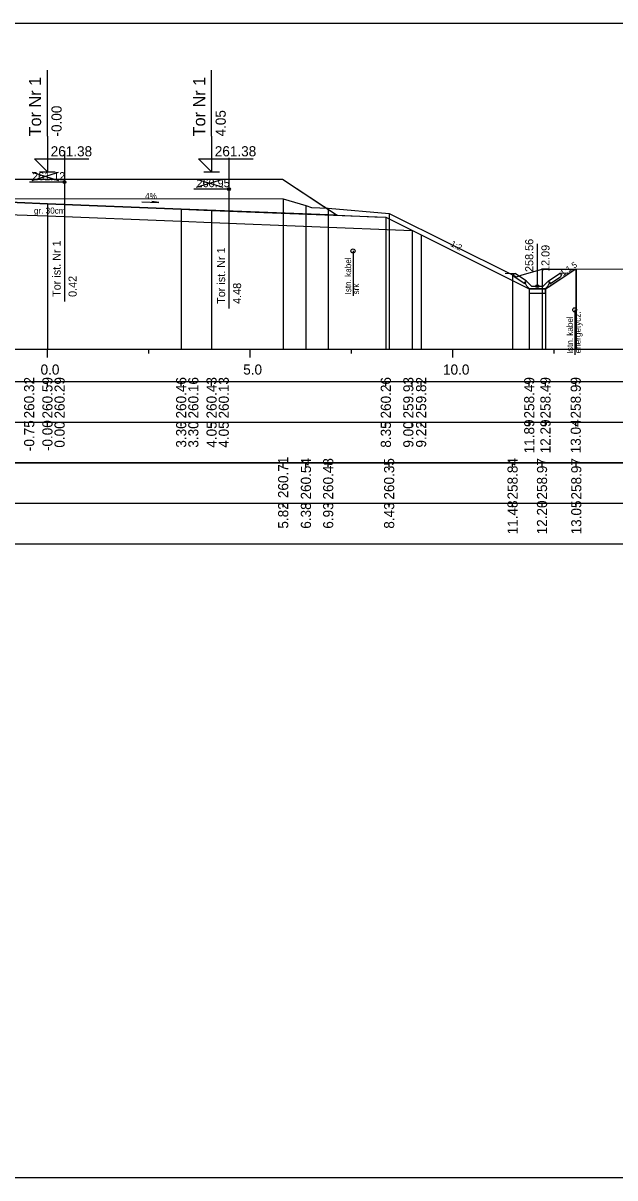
# Model space of a CAD drawing. Extents: x 6516023 to 6560129, y 5513077 to 5529206.
# Drawn here: x 6517492.86 to 6517507.46, y 5514484.66 to 5514513.16 of the extents above; entities that cross this region are included whole.
import ezdxf

# ---------------------------------------------------------------- set-up
doc = ezdxf.new("R2010")
doc.units = 0
for name, color, linetype in [('IR_default', 7, 'Continuous'), ('TOR_PRZEK_P-kable', 7, 'Continuous'), ('TOR_PRZEK_P-komponent', 7, 'Continuous'), ('TOR_PRZEK_P-odwodnienie', 7, 'Continuous'), ('TOR_PRZEK_P-opisy', 7, 'Continuous'), ('TOR_PRZEK_P-tabelka istniejace', 7, 'Continuous'), ('TOR_PRZEK_P-tabelka projektowane', 7, 'Continuous'), ('TOR_PRZEK_P-teren istniejacy', 7, 'Continuous'), ('TOR_PRZEK_P-tory istniejace', 7, 'Continuous'), ('TOR_PRZEK_P-tory projektowane', 7, 'Continuous'), ('TOR_PRZEK_P-uklad odniesienia', 7, 'Continuous'), ('TOR_PRZEK_P-warstwa ochronna I', 7, 'Continuous'), ('TOR_PRZEK_P-warstwa ochronna II', 7, 'Continuous'), ('TOR_RAMKI-ramka+tabelka 1', 7, 'Continuous')]:
    doc.layers.add(name, color=color, linetype=linetype)

msp = doc.modelspace()

# ---------------------------------------------------------------- linework, layer by layer
at = {"layer": 'IR_default'}
msp.add_lwpolyline([(6517491.713, 5514509.307), (6517494.429, 5514509.307), (6517495.213, 5514509.307), (6517495.336, 5514509.308), (6517495.763, 5514509.308), (6517498.479, 5514509.308), (6517499.263, 5514509.308), (6517500.307, 5514508.613), (6517500.608, 5514508.412), (6517501.543, 5514508.374), (6517501.813, 5514508.363), (6517502.488, 5514508.026), (6517502.683, 5514507.929), (6517503.278, 5514507.631), (6517505.352, 5514506.594), (6517505.441, 5514506.594), (6517505.752, 5514506.594), (6517505.883, 5514506.681), (6517506.337, 5514506.984), (6517506.373, 5514507.008), (6517506.499, 5514507.092)], dxfattribs=at)
at = {"layer": 'TOR_PRZEK_P-kable'}
for p, q in [((6517501.003, 5514507.533), (6517501.003, 5514506.423)), ((6517506.474, 5514506.08), (6517506.474, 5514504.97))]:
    msp.add_line(p, q, dxfattribs=at)
for centre in [(6517501.003, 5514507.533), (6517506.474, 5514506.08)]:
    msp.add_circle(centre, 0.05, dxfattribs=at)
at = {"layer": 'TOR_PRZEK_P-komponent'}
msp.add_lwpolyline([(6517487.213, 5514509.307), (6517490.713, 5514509.307), (6517491.713, 5514509.307), (6517495.213, 5514509.307), (6517495.763, 5514509.308), (6517499.263, 5514509.308), (6517500.608, 5514508.412), (6517496.763, 5514508.565), (6517493.463, 5514508.697), (6517492.713, 5514508.727), (6517491.513, 5514508.775), (6517490.913, 5514508.775), (6517489.713, 5514508.727), (6517488.963, 5514508.697), (6517486.128, 5514508.584)], close=True, dxfattribs=at)
at = {"layer": 'TOR_PRZEK_P-odwodnienie'}
for p, q in [((6517505.551, 5514506.664), (6517505.551, 5514507.708)), ((6517505.242, 5514506.723), (6517504.981, 5514506.897)), ((6517505.287, 5514506.79), (6517505.006, 5514506.977)), ((6517505.816, 5514506.79), (6517506.096, 5514506.977)), ((6517505.86, 5514506.723), (6517506.122, 5514506.897)), ((6517505.253, 5514506.74), (6517505.242, 5514506.723)), ((6517505.244, 5514506.759), (6517505.291, 5514506.783)), ((6517505.287, 5514506.79), (6517505.278, 5514506.777)), ((6517505.411, 5514506.664), (6517505.291, 5514506.783)), ((6517505.411, 5514506.664), (6517505.691, 5514506.664)), ((6517505.691, 5514506.664), (6517505.811, 5514506.783)), ((6517505.811, 5514506.783), (6517505.859, 5514506.759)), ((6517505.816, 5514506.79), (6517505.824, 5514506.777)), ((6517505.849, 5514506.74), (6517505.86, 5514506.723)), ((6517505.361, 5514506.594), (6517505.741, 5514506.594))]:
    msp.add_line(p, q, dxfattribs=at)
for points in [[(6517504.76, 5514506.988), (6517505.006, 5514506.977)], [(6517504.956, 5514506.95), (6517505.006, 5514506.977)], [(6517504.956, 5514506.95), (6517504.981, 5514506.897)], [(6517506.343, 5514506.988), (6517506.096, 5514506.977)], [(6517506.147, 5514506.95), (6517506.096, 5514506.977)], [(6517506.147, 5514506.95), (6517506.122, 5514506.897)], [(6517505.278, 5514506.777), (6517505.243, 5514506.759)], [(6517505.243, 5514506.759), (6517505.253, 5514506.74)], [(6517505.291, 5514506.664), (6517505.244, 5514506.759)], [(6517505.361, 5514506.594), (6517505.291, 5514506.664)], [(6517505.741, 5514506.594), (6517505.811, 5514506.664)], [(6517505.811, 5514506.664), (6517505.859, 5514506.759)], [(6517505.824, 5514506.777), (6517505.859, 5514506.759)], [(6517505.859, 5514506.759), (6517505.849, 5514506.74)], [(6517505.352, 5514506.594), (6517505.351, 5514506.595), (6517505.352, 5514506.594), (6517505.351, 5514506.594), (6517505.352, 5514506.594), (6517505.352, 5514506.594), (6517505.352, 5514506.594), (6517505.352, 5514506.595)], [(6517505.351, 5514506.594), (6517505.351, 5514506.594), (6517505.351, 5514506.594), (6517505.351, 5514506.593), (6517505.351, 5514506.594), (6517505.352, 5514506.593), (6517505.351, 5514506.594), (6517505.352, 5514506.594)], [(6517505.751, 5514506.594), (6517505.351, 5514506.594), (6517505.351, 5514506.494), (6517505.751, 5514506.494), (6517505.751, 5514506.594)], [(6517505.752, 5514506.594), (6517505.751, 5514506.595), (6517505.752, 5514506.594), (6517505.751, 5514506.594), (6517505.752, 5514506.594), (6517505.752, 5514506.594), (6517505.752, 5514506.594), (6517505.752, 5514506.595)], [(6517505.751, 5514506.594), (6517505.751, 5514506.594), (6517505.751, 5514506.594), (6517505.751, 5514506.593), (6517505.751, 5514506.594), (6517505.752, 5514506.593), (6517505.751, 5514506.594), (6517505.752, 5514506.594)]]:
    msp.add_lwpolyline(points, dxfattribs=at)
msp.add_circle((6517505.551, 5514506.664), 0.035, dxfattribs=at)
at = {"layer": 'TOR_PRZEK_P-opisy'}
msp.add_lwpolyline([(6517495.793, 5514508.745), (6517496.211, 5514508.726), (6517496.043, 5514508.754)], dxfattribs=at)
at = {"layer": 'TOR_PRZEK_P-tabelka istniejace'}
for p, q in [((6517499.28, 5514502.206), (6517499.28, 5514502.306)), ((6517499.841, 5514502.206), (6517499.841, 5514502.306)), ((6517500.39, 5514502.206), (6517500.39, 5514502.306)), ((6517501.894, 5514502.206), (6517501.894, 5514502.306)), ((6517504.94, 5514502.206), (6517504.94, 5514502.306)), ((6517505.666, 5514502.206), (6517505.666, 5514502.306)), ((6517506.512, 5514502.206), (6517506.512, 5514502.306)), ((6517454.663, 5514501.306), (6517538.463, 5514501.306)), ((6517499.28, 5514501.206), (6517499.28, 5514501.306)), ((6517499.841, 5514501.206), (6517499.841, 5514501.306)), ((6517500.39, 5514501.206), (6517500.39, 5514501.306)), ((6517501.894, 5514501.206), (6517501.894, 5514501.306)), ((6517504.94, 5514501.206), (6517504.94, 5514501.306)), ((6517505.666, 5514501.206), (6517505.666, 5514501.306)), ((6517506.512, 5514501.206), (6517506.512, 5514501.306))]:
    msp.add_line(p, q, dxfattribs=at)
for points in [[(6517499.28, 5514508.82), (6517499.28, 5514505.306), (6517499.28, 5514505.176), (6517499.28, 5514505.106)], [(6517499.841, 5514508.651), (6517499.841, 5514505.306), (6517499.841, 5514505.176), (6517499.841, 5514505.106)], [(6517500.39, 5514508.585), (6517500.39, 5514505.306), (6517500.39, 5514505.176), (6517500.39, 5514505.106)], [(6517501.894, 5514508.456), (6517501.894, 5514505.306), (6517501.894, 5514505.176), (6517501.894, 5514505.106)], [(6517504.94, 5514506.944), (6517504.94, 5514505.306), (6517504.94, 5514505.176), (6517504.94, 5514505.106)], [(6517505.666, 5514507.08), (6517505.666, 5514505.306), (6517505.666, 5514505.176), (6517505.666, 5514505.106)], [(6517506.512, 5514507.08), (6517506.512, 5514505.306), (6517506.512, 5514505.176), (6517506.512, 5514505.106)]]:
    msp.add_lwpolyline(points, dxfattribs=at)
msp.add_lwpolyline([(6517454.663, 5514502.306), (6517454.663, 5514500.306), (6517538.463, 5514500.306), (6517538.463, 5514502.306)], close=True, dxfattribs=at)
at = {"layer": 'TOR_PRZEK_P-tabelka projektowane'}
for p, q in [((6517493.463, 5514504.206), (6517493.463, 5514504.306)), ((6517493.463, 5514504.206), (6517493.463, 5514504.306)), ((6517496.763, 5514504.206), (6517496.763, 5514504.306)), ((6517496.763, 5514504.206), (6517496.763, 5514504.306)), ((6517497.513, 5514504.206), (6517497.513, 5514504.306)), ((6517497.513, 5514504.206), (6517497.513, 5514504.306)), ((6517501.813, 5514504.206), (6517501.813, 5514504.306)), ((6517502.465, 5514504.206), (6517502.465, 5514504.306)), ((6517502.683, 5514504.206), (6517502.683, 5514504.306)), ((6517505.351, 5514504.206), (6517505.351, 5514504.306)), ((6517505.751, 5514504.206), (6517505.751, 5514504.306)), ((6517506.498, 5514504.206), (6517506.498, 5514504.306)), ((6517454.663, 5514503.306), (6517538.463, 5514503.306)), ((6517493.463, 5514503.206), (6517493.463, 5514503.306)), ((6517493.463, 5514503.206), (6517493.463, 5514503.306)), ((6517496.763, 5514503.206), (6517496.763, 5514503.306)), ((6517496.763, 5514503.206), (6517496.763, 5514503.306)), ((6517497.513, 5514503.206), (6517497.513, 5514503.306)), ((6517497.513, 5514503.206), (6517497.513, 5514503.306)), ((6517501.813, 5514503.206), (6517501.813, 5514503.306)), ((6517502.465, 5514503.206), (6517502.465, 5514503.306)), ((6517502.683, 5514503.206), (6517502.683, 5514503.306)), ((6517505.351, 5514503.206), (6517505.351, 5514503.306)), ((6517505.751, 5514503.206), (6517505.751, 5514503.306)), ((6517506.498, 5514503.206), (6517506.498, 5514503.306))]:
    msp.add_line(p, q, dxfattribs=at)
for points in [[(6517493.463, 5514508.697), (6517493.463, 5514505.306), (6517493.463, 5514505.176), (6517493.463, 5514505.106)], [(6517493.463, 5514508.397), (6517493.463, 5514505.306), (6517493.463, 5514505.176), (6517493.463, 5514505.106)], [(6517496.763, 5514508.565), (6517496.763, 5514505.306), (6517496.763, 5514505.176), (6517496.763, 5514505.106)], [(6517497.513, 5514508.535), (6517497.513, 5514505.306), (6517497.513, 5514505.176), (6517497.513, 5514505.106)], [(6517501.813, 5514508.363), (6517501.813, 5514505.306), (6517501.813, 5514505.176), (6517501.813, 5514505.106)], [(6517496.763, 5514508.265), (6517496.763, 5514505.306), (6517496.763, 5514505.176), (6517496.763, 5514505.106)], [(6517497.513, 5514508.235), (6517497.513, 5514505.306), (6517497.513, 5514505.176), (6517497.513, 5514505.106)], [(6517502.465, 5514508.037), (6517502.465, 5514505.306), (6517502.465, 5514505.176), (6517502.465, 5514505.106)], [(6517502.683, 5514507.928), (6517502.683, 5514505.306), (6517502.683, 5514505.176), (6517502.683, 5514505.106)], [(6517506.498, 5514507.092), (6517506.498, 5514505.306), (6517506.498, 5514505.176), (6517506.498, 5514505.106)], [(6517505.351, 5514506.594), (6517505.351, 5514505.306), (6517505.351, 5514505.176), (6517505.351, 5514505.106)], [(6517505.751, 5514506.594), (6517505.751, 5514505.306), (6517505.751, 5514505.176), (6517505.751, 5514505.106)]]:
    msp.add_lwpolyline(points, dxfattribs=at)
msp.add_lwpolyline([(6517454.663, 5514504.306), (6517454.663, 5514502.306), (6517538.463, 5514502.306), (6517538.463, 5514504.306)], close=True, dxfattribs=at)
at = {"layer": 'TOR_PRZEK_P-teren istniejacy'}
msp.add_lwpolyline([(6517465.92, 5514507.405), (6517479.477, 5514507.197), (6517481.014, 5514507.158), (6517481.215, 5514507.031), (6517482.004, 5514506.639), (6517483.376, 5514507.541), (6517483.629, 5514507.725), (6517484.229, 5514507.774), (6517486.917, 5514508.006), (6517487.111, 5514508.155), (6517488.238, 5514508.828), (6517490.25, 5514508.824), (6517499.28, 5514508.82), (6517499.841, 5514508.651), (6517499.98, 5514508.608), (6517500.39, 5514508.585), (6517501.894, 5514508.456), (6517504.94, 5514506.944), (6517505.035, 5514506.898), (6517505.18, 5514506.94), (6517505.666, 5514507.08), (6517506.512, 5514507.08), (6517525.686, 5514507.094)], dxfattribs=at)
at = {"layer": 'TOR_PRZEK_P-tory istniejace'}
for p, q in [((6517493.883, 5514510.004), (6517493.883, 5514506.283)), ((6517497.941, 5514509.831), (6517497.941, 5514506.111)), ((6517493.084, 5514509.275), (6517493.736, 5514509.478)), ((6517493.084, 5514509.478), (6517493.736, 5514509.275)), ((6517493.884, 5514509.228), (6517493.018, 5514509.228)), ((6517497.142, 5514509.103), (6517497.794, 5514509.306)), ((6517497.142, 5514509.306), (6517497.794, 5514509.103)), ((6517497.942, 5514509.056), (6517497.076, 5514509.056))]:
    msp.add_line(p, q, dxfattribs=at)
for centre in [(6517493.884, 5514509.228), (6517497.942, 5514509.056)]:
    msp.add_circle(centre, 0.035, dxfattribs=at)
at = {"layer": 'TOR_PRZEK_P-tory projektowane'}
for p, q in [((6517493.463, 5514510.365), (6517493.463, 5514511.997)), ((6517497.513, 5514510.366), (6517497.513, 5514511.998)), ((6517493.463, 5514510.365), (6517493.463, 5514509.487)), ((6517497.513, 5514510.366), (6517497.513, 5514509.488)), ((6517493.463, 5514509.487), (6517493.144, 5514509.806)), ((6517493.144, 5514509.806), (6517494.488, 5514509.806)), ((6517497.513, 5514509.488), (6517497.194, 5514509.808)), ((6517497.194, 5514509.808), (6517498.538, 5514509.808)), ((6517493.271, 5514509.487), (6517493.655, 5514509.487)), ((6517497.321, 5514509.488), (6517497.705, 5514509.488))]:
    msp.add_line(p, q, dxfattribs=at)
at = {"layer": 'TOR_PRZEK_P-uklad odniesienia'}
for p, q in [((6517458.463, 5514505.106), (6517538.463, 5514505.106)), ((6517493.463, 5514504.906), (6517493.463, 5514505.106)), ((6517495.963, 5514505.006), (6517495.963, 5514505.106)), ((6517498.463, 5514504.906), (6517498.463, 5514505.106)), ((6517500.963, 5514505.006), (6517500.963, 5514505.106)), ((6517503.463, 5514504.906), (6517503.463, 5514505.106)), ((6517505.963, 5514505.006), (6517505.963, 5514505.106))]:
    msp.add_line(p, q, dxfattribs=at)
at = {"layer": 'TOR_PRZEK_P-warstwa ochronna I'}
msp.add_lwpolyline([(6517484.485, 5514508.218), (6517488.963, 5514508.397), (6517489.713, 5514508.427), (6517490.913, 5514508.475), (6517491.513, 5514508.475), (6517492.713, 5514508.427), (6517493.463, 5514508.397), (6517496.763, 5514508.265), (6517497.513, 5514508.235), (6517502.465, 5514508.037)], dxfattribs=at)
at = {"layer": 'TOR_PRZEK_P-warstwa ochronna II'}
msp.add_lwpolyline([(6517479.037, 5514507.203), (6517481.552, 5514507.316), (6517482.143, 5514506.922), (6517482.543, 5514506.922), (6517484.963, 5514508.537), (6517488.963, 5514508.697), (6517489.713, 5514508.727), (6517490.913, 5514508.775), (6517491.513, 5514508.775), (6517492.713, 5514508.727), (6517493.463, 5514508.697), (6517496.763, 5514508.565), (6517497.513, 5514508.535), (6517501.813, 5514508.363), (6517502.683, 5514507.928), (6517505.351, 5514506.594), (6517505.751, 5514506.594), (6517506.498, 5514507.092)], dxfattribs=at)
at = {"layer": 'TOR_RAMKI-ramka+tabelka 1'}
msp.add_lwpolyline([(6517452.013, 5514513.156), (6517699.513, 5514513.156), (6517699.513, 5514484.656), (6517452.013, 5514484.656)], close=True, dxfattribs=at)

# ---------------------------------------------------------------- texts
at = {"layer": 'TOR_PRZEK_P-kable'}
for s, height, p in [('Istn. kabel', 0.14999, (6517500.957, 5514506.459)), ('srk', 0.15, (6517501.152, 5514506.459)), ('Istn. kabel', 0.14999, (6517506.429, 5514505.006)), ('energetycz.', 0.14999, (6517506.623, 5514505.006))]:
    msp.add_text(s, height=height, rotation=90.0511, dxfattribs=at).set_placement(p)
at = {"layer": 'TOR_PRZEK_P-odwodnienie'}
for s, p in [('258.56', (6517505.451, 5514507.014)), ('12.09', (6517505.851, 5514507.014))]:
    msp.add_text(s, height=0.2, rotation=90, dxfattribs=at).set_placement(p)
at = {"layer": 'TOR_PRZEK_P-opisy'}
for s, rotation, p in [('4%', 359.8485, (6517495.872, 5514508.811)), ('1:2', 332.9299, (6517503.396, 5514507.661)), ('1:1,5', 34.0701, (6517506.181, 5514506.905))]:
    msp.add_text(s, height=0.15, rotation=rotation, dxfattribs=at).set_placement(p)
at = {"layer": 'TOR_PRZEK_P-tabelka istniejace'}
for s, p in [('260.71', (6517499.405, 5514501.433)), ('260.54', (6517499.966, 5514501.399)), ('260.48', (6517500.515, 5514501.398)), ('260.35', (6517502.019, 5514501.397)), ('258.84', (6517505.065, 5514501.399)), ('258.97', (6517505.791, 5514501.398)), ('258.97', (6517506.637, 5514501.398)), ('5.82', (6517499.405, 5514500.68)), ('6.38', (6517499.966, 5514500.677)), ('6.93', (6517500.515, 5514500.678)), ('8.43', (6517502.019, 5514500.678)), ('11.48', (6517505.065, 5514500.538)), ('12.20', (6517505.791, 5514500.538)), ('13.05', (6517506.637, 5514500.537))]:
    msp.add_text(s, height=0.25, rotation=90, dxfattribs=at).set_placement(p)
at = {"layer": 'TOR_PRZEK_P-tabelka projektowane'}
for s, p in [('260.32', (6517493.138, 5514503.4)), ('260.59', (6517493.588, 5514503.398)), ('260.29', (6517493.888, 5514503.398)), ('260.46', (6517496.888, 5514503.398)), ('260.16', (6517497.188, 5514503.398)), ('260.43', (6517497.638, 5514503.398)), ('260.13', (6517497.938, 5514503.398)), ('260.26', (6517501.938, 5514503.398)), ('259.93', (6517502.493, 5514503.398)), ('259.82', (6517502.808, 5514503.4)), ('258.49', (6517505.476, 5514503.398)), ('258.49', (6517505.876, 5514503.398)), ('258.99', (6517506.623, 5514503.398)), ('-0.75', (6517493.138, 5514502.593)), ('-0.00', (6517493.588, 5514502.594)), ('0.00', (6517493.888, 5514502.678)), ('3.30', (6517496.888, 5514502.678)), ('3.30', (6517497.188, 5514502.678)), ('4.05', (6517497.638, 5514502.677)), ('4.05', (6517497.938, 5514502.677)), ('8.35', (6517501.938, 5514502.677)), ('9.00', (6517502.493, 5514502.678)), ('9.22', (6517502.808, 5514502.68)), ('11.89', (6517505.476, 5514502.538)), ('12.29', (6517505.876, 5514502.538)), ('13.04', (6517506.623, 5514502.539))]:
    msp.add_text(s, height=0.25, rotation=90, dxfattribs=at).set_placement(p)
at = {"layer": 'TOR_PRZEK_P-tory istniejace'}
for s, p in [('261.12', (6517493.084, 5514509.278)), ('260.95', (6517497.142, 5514509.106))]:
    msp.add_text(s, height=0.2, dxfattribs=at).set_placement(p)
for s, rotation, p in [('Tor ist. Nr 1', 90.0511, (6517493.79, 5514506.398)), ('Tor ist. Nr 1', 90.0511, (6517497.848, 5514506.226)), ('0.42', 90, (6517494.184, 5514506.398)), ('4.48', 90, (6517498.242, 5514506.226))]:
    msp.add_text(s, height=0.2, rotation=rotation, dxfattribs=at).set_placement(p)
at = {"layer": 'TOR_PRZEK_P-tory projektowane'}
for s, height, p in [('Tor Nr 1', 0.3, (6517493.308, 5514510.359)), ('Tor Nr 1', 0.3, (6517497.358, 5514510.36)), ('-0.00', 0.25, (6517493.813, 5514510.357)), ('4.05', 0.25, (6517497.863, 5514510.358))]:
    msp.add_text(s, height=height, rotation=90, dxfattribs=at).set_placement(p)
for p in [(6517493.543, 5514509.867), (6517497.593, 5514509.868)]:
    msp.add_text('261.38', height=0.25, dxfattribs=at).set_placement(p)
at = {"layer": 'TOR_PRZEK_P-uklad odniesienia'}
for s, p in [('0.0', (6517493.294, 5514504.481)), ('5.0', (6517498.294, 5514504.481)), ('10.0', (6517503.224, 5514504.481))]:
    msp.add_text(s, height=0.25, dxfattribs=at).set_placement(p)
at = {"layer": 'TOR_PRZEK_P-warstwa ochronna I'}
msp.add_text('gr. 30cm', height=0.15, dxfattribs=at).set_placement((6517493.13, 5514508.454))

doc.saveas('drawing.dxf')
